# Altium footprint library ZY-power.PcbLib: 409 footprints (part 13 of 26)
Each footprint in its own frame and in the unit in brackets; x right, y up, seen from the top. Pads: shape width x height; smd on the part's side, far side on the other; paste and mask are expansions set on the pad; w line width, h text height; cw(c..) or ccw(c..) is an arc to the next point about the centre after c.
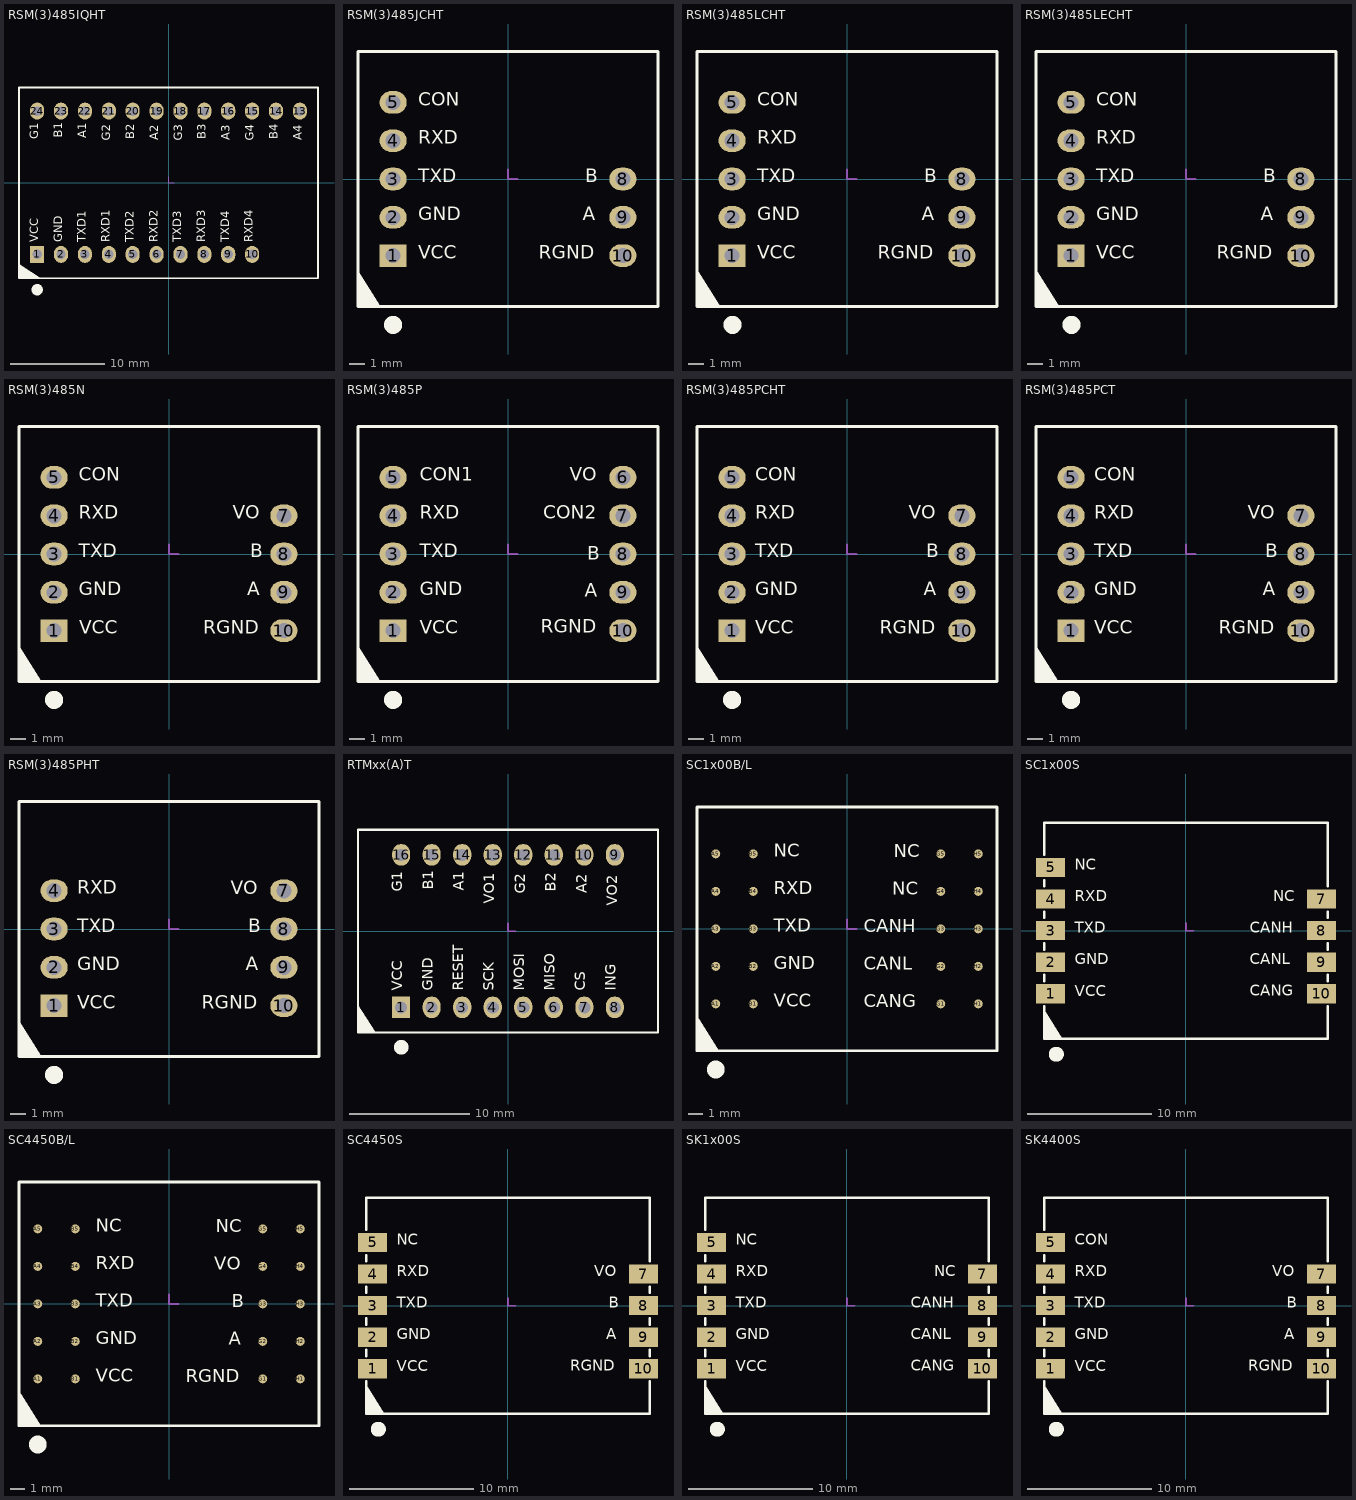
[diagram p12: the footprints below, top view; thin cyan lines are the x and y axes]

## RSM(3)485IQHT [mm]
height 9.5
pads (22):
  rect 1.5x1.8 hole 1: 1(-13.97,-7.62)
  oval 1.5x1.8 hole 1: 2(-11.43,-7.62) 3(-8.89,-7.62) 4(-6.35,-7.62) 5(-3.81,-7.62) 6(-1.27,-7.62) 7(1.27,-7.62) 8(3.81,-7.62) 9(6.35,-7.62) 10(8.89,-7.62) 13(13.97,7.62) 14(11.43,7.62) 15(8.89,7.62) 16(6.35,7.62) 17(3.81,7.62) 18(1.27,7.62) 19(-1.27,7.62) 20(-3.81,7.62) 21(-6.35,7.62) 22(-8.89,7.62) 23(-11.43,7.62) 24(-13.97,7.62)
Top Overlay:
  circle w1: c-13.97,-11.375 r0.1
  region: -13.57,-10.15 -15.9,-10.15 -15.9,-8.69
  lines w0.2: -15.9,-10.15 15.9,-10.15 15.9,10.15 -15.9,10.15 -15.9,-10.15
  text "VCC" at -13.538,-6.325 h1.52
  text "GND" at -11.001,-6.326 h1.52
  text "TXD1" at -8.464,-6.326 h1.52
  text "RXD1" at -5.927,-6.326 h1.52
  text "TXD2" at -3.389,-6.326 h1.52
  text "A4" at 14.478,4.524 h1.52
  text "B4" at 11.933,4.625 h1.52
  text "G4" at 9.389,4.448 h1.52
  text "A3" at 6.844,4.521 h1.52
  text "G1" at -13.513,4.632 h1.52
  text "B1" at -10.968,4.809 h1.52
  text "A1" at -8.424,4.708 h1.52
  text "B2" at -3.334,4.631 h1.52
  text "G2" at -5.879,4.454 h1.52
  text "RXD2" at -0.852,-6.326 h1.52
  text "TXD3" at 1.685,-6.326 h1.52
  text "RXD3" at 4.222,-6.326 h1.52
  text "TXD4" at 6.759,-6.326 h1.52
  text "RXD4" at 9.296,-6.326 h1.52
  text "B3" at 4.3,4.622 h1.52
  text "G3" at 1.755,4.445 h1.52
  text "A2" at -0.79,4.53 h1.52
Mechanical 15:
  lines w0.127: 0,0.635 0,0 0.635,0

## RSM(3)485JCHT [mm]
height 7.1
pads (8):
  rect 1.8x1.5 hole 1: 1(-7.62,-5.08)
  oval 1.8x1.5 hole 1: 2(-7.62,-2.54) 3(-7.62,0) 4(-7.62,2.54) 5(-7.62,5.08) 8(7.62,0) 9(7.62,-2.54) 10(7.62,-5.08)
Top Overlay:
  circle w1: c-7.62,-9.675 r0.1
  region: -9.95,-6.12 -9.95,-8.45 -8.49,-8.45
  lines w0.2: -9.95,-8.45 9.95,-8.45 9.95,8.45 -9.95,8.45 -9.95,-8.45
  text "A" at 4.952,-3.048 h1.52
  text "B" at 5.126,-0.508 h1.52
  text "RGND" at 2.032,-5.588 h1.52
  text "CON" at -5.939,4.572 h1.52
  text "RXD" at -5.939,2.032 h1.52
  text "TXD" at -5.939,-0.508 h1.52
  text "VCC" at -5.938,-5.588 h1.52
  text "GND" at -5.939,-3.048 h1.52
Mechanical 15:
  lines w0.127: 0,0.635 0,0 0.635,0
3D body "zhen01.stp": height 6.09, standoff -4.41, extent -7.87,4.83 -7.37,5.33
3D body "zhen01.stp": height 6.09, standoff -4.41, extent -7.87,2.29 -7.37,2.79
3D body "zhen01.stp": height 6.09, standoff -4.41, extent -7.87,-0.25 -7.37,0.25
3D body "zhen01.stp": height 6.09, standoff -4.41, extent -7.87,-2.79 -7.37,-2.29
3D body "zhen01.stp": height 6.09, standoff -4.41, extent -7.87,-5.33 -7.37,-4.83
3D body "zhen01.stp": height 6.09, standoff -4.41, extent 7.37,-0.25 7.87,0.25
3D body "zhen01.stp": height 6.09, standoff -4.41, extent 7.37,-2.79 7.87,-2.29
3D body "zhen01.stp": height 6.09, standoff -4.41, extent 7.37,-5.33 7.87,-4.83
3D body: height 7.1, standoff 0, extent -9.95,-8.45 9.95,8.45

## RSM(3)485LCHT [mm]
height 7.1
pads (8):
  rect 1.8x1.5 hole 1: 1(-7.62,-5.08)
  oval 1.8x1.5 hole 1: 2(-7.62,-2.54) 3(-7.62,0) 4(-7.62,2.54) 5(-7.62,5.08) 8(7.62,0) 9(7.62,-2.54) 10(7.62,-5.08)
Top Overlay:
  circle w1: c-7.593,-9.675 r0.1
  region: -9.95,-6.223 -9.95,-8.45 -8.49,-8.45 -9.838,-6.298
  lines w0.15: -9.95,-6.12 -8.49,-8.45
  lines w0.2: -9.95,-8.45 9.95,-8.45 9.95,8.45 -9.95,8.45 -9.95,-8.45
  text "GND" at -5.939,-3.048 h1.52
  text "VCC" at -5.938,-5.588 h1.52
  text "TXD" at -5.939,-0.508 h1.52
  text "RXD" at -5.939,2.032 h1.52
  text "CON" at -5.939,4.572 h1.52
  text "B" at 5.126,-0.508 h1.52
  text "A" at 4.952,-3.048 h1.52
  text "RGND" at 2.032,-5.588 h1.52
Mechanical 15:
  lines w0.127: 0,0.635 0,0 0.635,0

## RSM(3)485LECHT [mm]
height 7.1
pads (8):
  rect 1.8x1.5 hole 1: 1(-7.62,-5.08)
  oval 1.8x1.5 hole 1: 2(-7.62,-2.54) 3(-7.62,0) 4(-7.62,2.54) 5(-7.62,5.08) 8(7.62,0) 9(7.62,-2.54) 10(7.62,-5.08)
Top Overlay:
  circle w1: c-7.593,-9.675 r0.1
  region: -9.95,-6.223 -9.95,-8.45 -8.49,-8.45 -9.838,-6.298
  lines w0.15: -9.95,-6.12 -8.49,-8.45
  lines w0.2: -9.95,-8.45 9.95,-8.45 9.95,8.45 -9.95,8.45 -9.95,-8.45
  text "GND" at -5.939,-3.048 h1.52
  text "VCC" at -5.938,-5.588 h1.52
  text "TXD" at -5.939,-0.508 h1.52
  text "RXD" at -5.939,2.032 h1.52
  text "CON" at -5.939,4.572 h1.52
  text "B" at 5.126,-0.508 h1.52
  text "A" at 4.952,-3.048 h1.52
  text "RGND" at 2.032,-5.588 h1.52
Mechanical 15:
  lines w0.127: 0,0.635 0,0 0.635,0

## RSM(3)485N [mm]
height 7.05
pads (9):
  rect 1.8x1.5 hole 1: 1(-7.62,-5.08)
  oval 1.8x1.5 hole 1: 2(-7.62,-2.54) 3(-7.62,0) 4(-7.62,2.54) 5(-7.62,5.08) 7(7.62,2.54) 8(7.62,0) 9(7.62,-2.54) 10(7.62,-5.08)
Top Overlay:
  circle w1: c-7.62,-9.675 r0.1
  region: -9.95,-6.12 -9.95,-8.45 -8.49,-8.45
  lines w0.2: -9.95,-8.45 9.95,-8.45 9.95,8.45 -9.95,8.45 -9.95,-8.45
  text "A" at 5.206,-3.048 h1.52
  text "B" at 5.38,-0.508 h1.52
  text "RGND" at 2.286,-5.588 h1.52
  text "TXD" at -5.97,-0.508 h1.52
  text "RXD" at -5.97,2.032 h1.52
  text "GND" at -5.97,-3.048 h1.52
  text "CON" at -5.97,4.572 h1.52
  text "VCC" at -5.969,-5.588 h1.52
  text "VO" at 4.215,2.032 h1.52
Mechanical 15:
  lines w0.127: 0,0.635 0,0 0.635,0

## RSM(3)485P [mm]
height 7.05
pads (10):
  rect 1.8x1.5 hole 1: 1(-7.62,-5.08)
  oval 1.8x1.5 hole 1: 2(-7.62,-2.54) 3(-7.62,0) 4(-7.62,2.54) 5(-7.62,5.08) 6(7.62,5.08) 7(7.62,2.54) 8(7.62,0) 9(7.62,-2.54) 10(7.62,-5.08)
Top Overlay:
  circle w1: c-7.62,-9.675 r0.1
  region: -9.95,-6.12 -9.95,-8.45 -8.49,-8.45
  lines w0.2: -9.95,-8.45 9.95,-8.45 9.95,8.45 -9.95,8.45 -9.95,-8.45
  text "VO" at 4.088,4.572 h1.52
  text "CON2" at 2.345,2.032 h1.52
  text "VCC" at -5.842,-5.588 h1.52
  text "GND" at -5.843,-3.023 h1.52
  text "TXD" at -5.843,-0.508 h1.52
  text "RXD" at -5.843,2.032 h1.52
  text "CON1" at -5.843,4.572 h1.52
  text "B" at 5.253,-0.686 h1.52
  text "A" at 5.079,-3.124 h1.52
  text "RGND" at 2.159,-5.537 h1.52
Mechanical 15:
  lines w0.127: 0,0.635 0,0 0.635,0

## RSM(3)485PCHT [mm]
height 7.05
pads (9):
  rect 1.8x1.5 hole 1: 1(-7.62,-5.08)
  oval 1.8x1.5 hole 1: 2(-7.62,-2.54) 3(-7.62,0) 4(-7.62,2.54) 5(-7.62,5.08) 7(7.62,2.54) 8(7.62,0) 9(7.62,-2.54) 10(7.62,-5.08)
Top Overlay:
  circle w1: c-7.62,-9.675 r0.1
  region: -9.95,-6.12 -9.95,-8.45 -8.49,-8.45
  lines w0.2: -9.95,-8.45 -9.95,8.45 9.95,8.45 9.95,-8.45 -9.95,-8.45
  text "A" at 5.079,-3.048 h1.52
  text "B" at 5.253,-0.508 h1.52
  text "RGND" at 2.159,-5.588 h1.52
  text "TXD" at -6.097,-0.508 h1.52
  text "RXD" at -6.097,2.032 h1.52
  text "GND" at -6.097,-3.048 h1.52
  text "CON" at -6.097,4.572 h1.52
  text "VCC" at -6.096,-5.588 h1.52
  text "VO" at 4.088,2.032 h1.52
Mechanical 15:
  lines w0.127: 0,0.635 0,0 0.635,0

## RSM(3)485PCT [mm]
height 7.05
pads (9):
  rect 1.8x1.5 hole 1: 1(-7.62,-5.08)
  oval 1.8x1.5 hole 1: 2(-7.62,-2.54) 3(-7.62,0) 4(-7.62,2.54) 5(-7.62,5.08) 7(7.62,2.54) 8(7.62,0) 9(7.62,-2.54) 10(7.62,-5.08)
Top Overlay:
  circle w1: c-7.62,-9.675 r0.1
  region: -9.95,-6.12 -9.95,-8.45 -8.49,-8.45
  lines w0.2: -9.95,-8.45 -9.95,8.45 9.95,8.45 9.95,-8.45 -9.95,-8.45
  text "VO" at 4.088,2.032 h1.52
  text "VCC" at -6.096,-5.588 h1.52
  text "CON" at -6.097,4.572 h1.52
  text "GND" at -6.097,-3.048 h1.52
  text "RXD" at -6.097,2.032 h1.52
  text "TXD" at -6.097,-0.508 h1.52
  text "RGND" at 2.159,-5.588 h1.52
  text "B" at 5.253,-0.508 h1.52
  text "A" at 5.079,-3.048 h1.52
Mechanical 15:
  lines w0.127: 0,0.635 0,0 0.635,0

## RSM(3)485PHT [mm]
height 7.05
pads (8):
  rect 1.8x1.5 hole 1: 1(-7.62,-5.08)
  oval 1.8x1.5 hole 1: 2(-7.62,-2.54) 3(-7.62,0) 4(-7.62,2.54) 7(7.62,2.54) 8(7.62,0) 9(7.62,-2.54) 10(7.62,-5.08)
Top Overlay:
  circle w1: c-7.62,-9.675 r0.1
  region: -9.95,-6.12 -9.95,-8.45 -8.49,-8.45
  lines w0.2: -9.95,-8.45 9.95,-8.45 9.95,8.45 -9.95,8.45 -9.95,-8.45
  text "VO" at 4.088,2.007 h1.52
  text "A" at 5.079,-3.048 h1.52
  text "B" at 5.253,-0.508 h1.52
  text "RGND" at 2.159,-5.588 h1.52
  text "TXD" at -6.097,-0.508 h1.52
  text "RXD" at -6.097,2.032 h1.52
  text "GND" at -6.097,-3.048 h1.52
  text "VCC" at -6.096,-5.588 h1.52
Mechanical 15:
  lines w0.127: 0,0.635 0,0 0.635,0
3D body: height 7.1, standoff 0, extent -9.95,-8.45 9.95,8.45
3D body "zhen01.stp": height 6.09, standoff -4.41, extent 7.37,-5.33 7.87,-4.83
3D body "zhen01.stp": height 6.09, standoff -4.41, extent 7.37,-2.79 7.87,-2.29
3D body "zhen01.stp": height 6.09, standoff -4.41, extent 7.37,-0.25 7.87,0.25
3D body "zhen01.stp": height 6.09, standoff -4.41, extent -7.87,-5.33 -7.37,-4.83
3D body "zhen01.stp": height 6.09, standoff -4.41, extent -7.87,-2.79 -7.37,-2.29
3D body "zhen01.stp": height 6.09, standoff -4.41, extent -7.87,-0.25 -7.37,0.25
3D body "zhen01.stp": height 6.09, standoff -4.41, extent -7.87,2.29 -7.37,2.79
3D body "zhen01.stp": height 6.09, standoff -4.41, extent 7.37,2.29 7.87,2.79

## RTMxx(A)T [mm]
height 7.1
pads (16):
  rect 1.5x1.8 hole 1: 1(-8.89,-6.35)
  oval 1.5x1.8 hole 1: 2(-6.35,-6.35) 3(-3.81,-6.35) 4(-1.27,-6.35) 5(1.27,-6.35) 6(3.81,-6.35) 7(6.35,-6.35) 8(8.89,-6.35) 9(8.89,6.35) 10(6.35,6.35) 11(3.81,6.35) 12(1.27,6.35) 13(-1.27,6.35) 14(-3.81,6.35) 15(-6.35,6.35) 16(-8.89,6.35)
Top Overlay:
  circle w1: c-8.89,-9.675 r0.1
  region: -12.49,-6.12 -12.49,-8.45 -11.03,-8.45
  lines w0.2: -12.49,-8.45 -12.49,8.45 12.49,8.45 12.49,-8.45 -12.49,-8.45
  text "VO2" at 9.398,2.11 h1.52
  text "ING" at 9.271,-4.953 h1.52
  text "CS" at 6.731,-4.953 h1.52
  text "VCC" at -8.509,-4.953 h1.52
  text "A2" at 6.84,3.162 h1.52
  text "GND" at -5.969,-4.953 h1.52
  text "RESET" at -3.429,-4.953 h1.52
  text "SCK" at -0.889,-4.953 h1.52
  text "MOSI" at 1.651,-4.953 h1.52
  text "MISO" at 4.191,-4.953 h1.52
  text "B2" at 4.282,3.263 h1.52
  text "G2" at 1.724,3.086 h1.52
  text "VO1" at -0.835,2.289 h1.52
  text "A1" at -3.393,3.341 h1.52
  text "B1" at -5.951,3.442 h1.52
  text "G1" at -8.509,3.265 h1.52
Mechanical 15:
  lines w0.127: 0,0.635 0,0 0.635,0

## SC1x00B/L [mm]
height 5.5
pads (20):
  round 0.61 smd: A1(-8.89,-5.08) A2(-8.89,-2.54) A3(-8.89,0) A4(-8.89,2.54) A5(-8.89,5.08) B1(-6.35,-5.08) B2(-6.35,-2.54) B3(-6.35,0) B4(-6.35,2.54) B5(-6.35,5.08) G1(6.35,-5.08) G2(6.35,-2.54) G3(6.35,0) G4(6.35,2.54) G5(6.35,5.08) H1(8.89,-5.08) H2(8.89,-2.54) H3(8.89,0) H4(8.89,2.54) H5(8.89,5.08)
Top Overlay:
  circle w1: c-8.89,-9.525 r0.1
  region: -10.16,-5.925 -10.16,-8.255 -8.7,-8.255
  lines w0.2: -10.16,-8.255 10.16,-8.255 10.16,8.255 -10.16,8.255 -10.16,-8.255
  text "CANG" at 1.143,-5.604 h1.52
  text "CANL" at 1.143,-3.064 h1.52
  text "CANH" at 1.143,-0.524 h1.52
  text "NC" at 3.072,2.016 h1.52
  text "NC" at 3.164,4.556 h1.52
  text "NC" at -4.954,4.572 h1.52
  text "RXD" at -4.954,2.032 h1.52
  text "TXD" at -4.954,-0.508 h1.52
  text "GND" at -4.954,-3.048 h1.52
  text "VCC" at -4.953,-5.588 h1.52
Mechanical 15:
  lines w0.127: 0,0.635 0,0 0.635,0

## SC1x00S [mm]
height 5.5
pads (9):
  rect 2.35x1.55 smd: 1(-10.9,-5.08) 2(-10.9,-2.54) 3(-10.9,0) 4(-10.9,2.54) 5(-10.9,5.08) 7(10.9,2.54) 8(10.9,0) 9(10.9,-2.54) 10(10.9,-5.08)
Top Overlay:
  circle w1: c-10.438,-9.953 r0.1
  region: -11.43,-6.37 -11.43,-8.7 -9.97,-8.7
  lines w0.2: -11.43,-6.096 -11.43,-8.7 11.43,-8.7 11.43,-6.096 ; -11.43,-4.064 -11.43,-3.556 ; -11.43,-1.524 -11.43,-1.016 ; -11.43,1.016 -11.43,1.524 ; -11.43,3.556 -11.43,4.064 ; -11.43,6.096 -11.43,8.7 11.43,8.7 11.43,3.556 ; 11.43,-4.064 11.43,-3.556 ; 11.43,-1.524 11.43,-1.016 ; 11.43,1.016 11.43,1.524
  text "VCC" at -8.965,-5.588 h1.52
  text "GND" at -8.965,-3.048 h1.52
  text "TXD" at -8.965,-0.508 h1.52
  text "RXD" at -8.965,2.032 h1.52
  text "NC" at -8.965,4.572 h1.52
  text "NC" at 7.004,2.048 h1.52
  text "CANH" at 5.132,-0.492 h1.52
  text "CANL" at 5.132,-3.032 h1.52
  text "CANG" at 5.132,-5.572 h1.52
Mechanical 15:
  lines w0.127: 0,0.635 0,0 0.635,0

## SC4450B/L [mm]
height 6
pads (20):
  round 0.61 smd: A1(-8.89,-5.08) A2(-8.89,-2.54) A3(-8.89,0) A4(-8.89,2.54) A5(-8.89,5.08) B1(-6.35,-5.08) B2(-6.35,-2.54) B3(-6.35,0) B4(-6.35,2.54) B5(-6.35,5.08) G1(6.35,-5.08) G2(6.35,-2.54) G3(6.35,0) G4(6.35,2.54) G5(6.35,5.08) H1(8.89,-5.08) H2(8.89,-2.54) H3(8.89,0) H4(8.89,2.54) H5(8.89,5.08)
Top Overlay:
  circle w1: c-8.89,-9.525 r0.1
  region: -10.16,-5.925 -10.16,-8.255 -8.7,-8.255
  lines w0.2: -10.16,-8.255 10.16,-8.255 10.16,8.255 -10.16,8.255 -10.16,-8.255
  text "RGND" at 1.143,-5.604 h1.52
  text "A" at 4.063,-3.064 h1.52
  text "B" at 4.237,-0.524 h1.52
  text "VO" at 3.072,2.016 h1.52
  text "NC" at 3.164,4.556 h1.52
  text "NC" at -4.954,4.572 h1.52
  text "RXD" at -4.954,2.032 h1.52
  text "TXD" at -4.954,-0.508 h1.52
  text "GND" at -4.954,-3.048 h1.52
  text "VCC" at -4.953,-5.588 h1.52
Mechanical 15:
  lines w0.127: 0,0.635 0,0 0.635,0

## SC4450S [mm]
height 5.5
pads (9):
  rect 2.35x1.55 smd: 1(-10.9,-5.08) 2(-10.9,-2.54) 3(-10.9,0) 4(-10.9,2.54) 5(-10.9,5.08) 7(10.9,2.54) 8(10.9,0) 9(10.9,-2.54) 10(10.9,-5.08)
Top Overlay:
  circle w1: c-10.438,-9.953 r0.1
  region: -11.43,-6.37 -11.43,-8.7 -9.97,-8.7
  lines w0.2: -11.43,-6.096 -11.43,-8.7 11.43,-8.7 11.43,-6.096 ; -11.43,-4.064 -11.43,-3.556 ; -11.43,-1.524 -11.43,-1.016 ; -11.43,1.016 -11.43,1.524 ; -11.43,3.556 -11.43,4.064 ; -11.43,6.096 -11.43,8.7 11.43,8.7 11.43,3.556 ; 11.43,-4.064 11.43,-3.556 ; 11.43,-1.524 11.43,-1.016 ; 11.43,1.016 11.43,1.524
  text "RGND" at 5.005,-5.572 h1.52
  text "A" at 7.925,-3.032 h1.52
  text "B" at 8.098,-0.492 h1.52
  text "VO" at 6.933,2.048 h1.52
  text "NC" at -8.965,4.572 h1.52
  text "RXD" at -8.965,2.032 h1.52
  text "TXD" at -8.965,-0.508 h1.52
  text "GND" at -8.965,-3.048 h1.52
  text "VCC" at -8.965,-5.588 h1.52
Mechanical 15:
  lines w0.127: 0,0.635 0,0 0.635,0

## SK1x00S [mm]
height 5.5
pads (9):
  rect 2.35x1.55 smd: 1(-10.9,-5.08) 2(-10.9,-2.54) 3(-10.9,0) 4(-10.9,2.54) 5(-10.9,5.08) 7(10.9,2.54) 8(10.9,0) 9(10.9,-2.54) 10(10.9,-5.08)
Top Overlay:
  circle w1: c-10.438,-9.953 r0.1
  region: -11.43,-6.37 -11.43,-8.7 -9.97,-8.7
  lines w0.2: -11.43,-6.096 -11.43,-8.7 11.43,-8.7 11.43,-6.096 ; -11.43,-4.064 -11.43,-3.556 ; -11.43,-1.524 -11.43,-1.016 ; -11.43,1.016 -11.43,1.524 ; -11.43,3.556 -11.43,4.064 ; -11.43,6.096 -11.43,8.7 11.43,8.7 11.43,3.556 ; 11.43,-4.064 11.43,-3.556 ; 11.43,-1.524 11.43,-1.016 ; 11.43,1.016 11.43,1.524
  text "CANG" at 5.132,-5.572 h1.52
  text "CANL" at 5.132,-3.032 h1.52
  text "CANH" at 5.132,-0.492 h1.52
  text "NC" at 7.004,2.048 h1.52
  text "NC" at -8.965,4.572 h1.52
  text "RXD" at -8.965,2.032 h1.52
  text "TXD" at -8.965,-0.508 h1.52
  text "GND" at -8.965,-3.048 h1.52
  text "VCC" at -8.965,-5.588 h1.52
Mechanical 15:
  lines w0.127: 0,0.635 0,0 0.635,0

## SK4400S [mm]
height 3.9
pads (9):
  rect 2.35x1.55 smd: 1(-10.9,-5.08) 2(-10.9,-2.54) 3(-10.9,0) 4(-10.9,2.54) 5(-10.9,5.08) 7(10.9,2.54) 8(10.9,0) 9(10.9,-2.54) 10(10.9,-5.08)
Top Overlay:
  circle w1: c-10.438,-9.953 r0.1
  region: -11.43,-6.37 -11.43,-8.7 -9.97,-8.7
  lines w0.2: -11.43,-6.096 -11.43,-8.7 11.43,-8.7 11.43,-6.096 ; -11.43,-4.064 -11.43,-3.556 ; -11.43,-1.524 -11.43,-1.016 ; -11.43,1.016 -11.43,1.524 ; -11.43,3.556 -11.43,4.064 ; -11.43,6.096 -11.43,8.7 11.43,8.7 11.43,3.556 ; 11.43,-4.064 11.43,-3.556 ; 11.43,-1.524 11.43,-1.016 ; 11.43,1.016 11.43,1.524
  text "VCC" at -8.965,-5.588 h1.52
  text "GND" at -8.965,-3.048 h1.52
  text "TXD" at -8.965,-0.508 h1.52
  text "RXD" at -8.965,2.032 h1.52
  text "CON" at -8.965,4.572 h1.52
  text "VO" at 6.933,2.048 h1.52
  text "B" at 8.098,-0.492 h1.52
  text "A" at 7.925,-3.032 h1.52
  text "RGND" at 5.005,-5.572 h1.52
Mechanical 15:
  lines w0.127: 0,0.635 0,0 0.635,0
